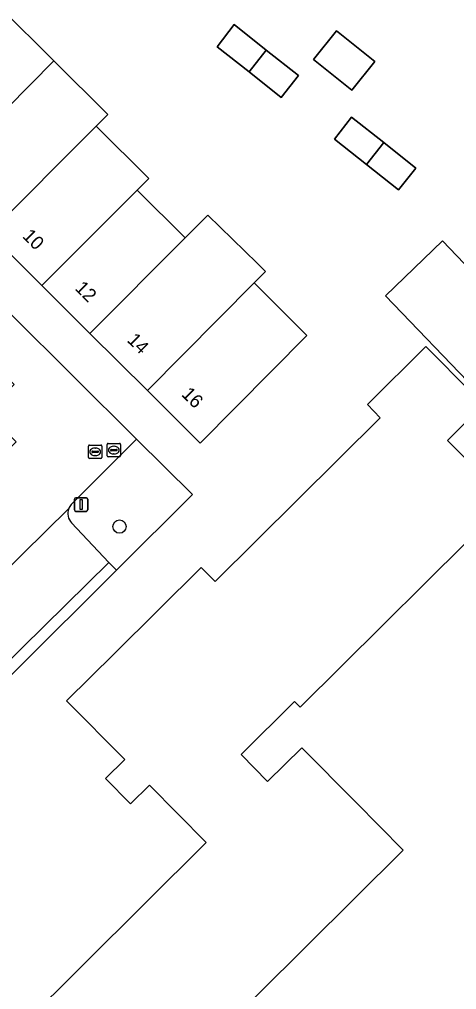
# Model space of a CAD drawing. Extents: x 159217 to 160349, y 381246 to 382172.
# Drawn here: x 160136.7 to 160169.1, y 381809.4 to 381881.2 of the extents above; entities that cross this region are included whole.
import ezdxf

# ---------------------------------------------------------------- set-up
doc = ezdxf.new("R2010")
doc.units = 0
for name, color, linetype in [('IMGEO_Boom', 7, 'Continuous'), ('IMGEO_Erf', 7, 'Continuous'), ('IMGEO_Groenvoorziening', 7, 'Continuous'), ('IMGEO_Lichtmast', 7, 'Continuous'), ('IMGEO_Pand', 7, 'Continuous'), ('IMGEO_Pand_nummerreeks', 7, 'Continuous'), ('IMGEO_Parkeervlak_open', 7, 'Continuous'), ('IMGEO_Rijbaan_lokaal_open', 7, 'Continuous'), ('IMGEO_Rioolput', 7, 'Continuous')]:
    doc.layers.add(name, color=color, linetype=linetype)

msp = doc.modelspace()

# ---------------------------------------------------------------- linework, layer by layer
at = {"layer": 'IMGEO_Boom'}
msp.add_circle((160144.146, 381843.679), 0.489, dxfattribs=at)
at = {"layer": 'IMGEO_Erf'}
for points in [[(160135.289, 381882.107), (160139.285, 381878.145), (160143.281, 381874.182), (160142.426, 381873.326), (160146.318, 381869.443), (160145.46, 381868.584), (160149.006, 381865.046), (160150.699, 381866.743), (160154.339, 381863.189), (160154.967, 381862.561), (160154.123, 381861.711), (160158.032, 381857.827), (160150.125, 381849.867), (160146.217, 381853.749), (160141.958, 381857.981), (160138.4, 381861.516), (160134.5, 381865.391), (160130.54, 381869.325), (160126.548, 381873.292), (160122.556, 381877.258), (160118.566, 381881.222), (160122.789, 381885.483)], [(160113.448, 381881.888), (160122.049, 381873.351), (160145.414, 381850.161), (160149.552, 381846.054), (160143.934, 381840.463), (160128.998, 381825.598), (160127.968, 381824.573), (160119.351, 381815.997), (160108.166, 381805.405)], [(160170.544, 381853.806), (160163.848, 381860.771), (160168.067, 381864.827), (160171.262, 381861.503)], [(160132.354, 381802.21), (160150.581, 381820.291), (160146.369, 381824.537), (160144.966, 381823.146), (160143.105, 381825.021), (160144.532, 381826.436), (160140.234, 381830.77), (160143.784, 381834.292), (160150.198, 381840.654), (160151.235, 381839.608), (160163.467, 381851.742), (160162.511, 381852.705), (160166.847, 381857.005), (160170.276, 381853.549)], [(160171.111, 381852.706), (160168.443, 381850.059), (160172.909, 381845.556), (160157.539, 381830.31), (160157.119, 381830.734), (160153.152, 381826.799), (160155.124, 381824.811), (160157.648, 381827.314), (160161.653, 381823.277), (160165.174, 381819.727), (160140.052, 381794.807)]]:
    msp.add_lwpolyline(points, dxfattribs=at)
for points in [[(160151.385, 381879.202), (160152.631, 381880.839), (160155.019, 381878.952), (160157.407, 381877.065), (160156.132, 381875.451), (160153.744, 381877.338)], [(160158.532, 381878.263), (160160.228, 381880.375), (160163.054, 381878.105), (160161.359, 381875.993)], [(160160.075, 381872.356), (160161.338, 381873.983), (160163.719, 381872.102), (160166.099, 381870.221), (160164.822, 381868.605), (160162.442, 381870.486)]]:
    msp.add_lwpolyline(points, close=True, dxfattribs=at)
at = {"layer": 'IMGEO_Groenvoorziening'}
for points in [[(160145.414, 381850.161), (160140.579, 381845.323)], [(160140.604, 381843.948), (160143.366, 381841.03), (160143.934, 381840.463), (160149.552, 381846.054), (160145.414, 381850.161)]]:
    msp.add_lwpolyline(points, dxfattribs=at)
msp.add_lwpolyline([(160143.934, 381840.463), (160143.366, 381841.03), (160127.317, 381825.26), (160127.968, 381824.573), (160128.998, 381825.598)], close=True, dxfattribs=at)
for centre, radius, start, end in [((160141.315, 381844.649), 0.999, 158.51437, 224.58012), ((160141.338, 381844.633), 1.026, 137.72838, 158.12718)]:
    msp.add_arc(centre, radius, start, end, dxfattribs=at)
at = {"layer": 'IMGEO_Lichtmast'}
for p, q in [((160140.804, 381844.908), (160140.804, 381845.708)), ((160140.804, 381845.708), (160140.804, 381844.908)), ((160140.904, 381845.808), (160141.694, 381845.808)), ((160141.694, 381845.808), (160140.904, 381845.808)), ((160141.794, 381845.708), (160141.794, 381844.908)), ((160141.794, 381844.908), (160141.794, 381845.708)), ((160141.694, 381844.808), (160140.904, 381844.808)), ((160140.904, 381844.808), (160141.694, 381844.808))]:
    msp.add_line(p, q, dxfattribs=at)
msp.add_lwpolyline([(160141.224, 381845.683), (160141.374, 381845.683), (160141.374, 381844.933), (160141.224, 381844.933), (160141.224, 381845.683)], dxfattribs=at)
for centre, start, end in [((160140.904, 381845.708), 90, 180), ((160140.904, 381845.708), 90, 180), ((160141.694, 381845.708), 0, 90), ((160141.694, 381845.708), 360, 90), ((160140.904, 381844.908), 180, 270), ((160140.904, 381844.908), 180, 270), ((160141.694, 381844.908), 270, 0), ((160141.694, 381844.908), 270, 0)]:
    msp.add_arc(centre, 0.1, start, end, dxfattribs=at)
at = {"layer": 'IMGEO_Pand'}
for points in [[(160139.285, 381878.145), (160135.289, 381882.107), (160126.548, 381873.292), (160130.54, 381869.325)], [(160152.631, 381880.839), (160151.385, 381879.202), (160153.744, 381877.338), (160155.019, 381878.952)], [(160158.532, 381878.263), (160161.359, 381875.993), (160163.054, 381878.105), (160160.228, 381880.375)], [(160155.019, 381878.952), (160153.744, 381877.338), (160156.132, 381875.451), (160157.407, 381877.065)], [(160142.426, 381873.326), (160143.281, 381874.182), (160139.285, 381878.145), (160130.54, 381869.325), (160134.5, 381865.391)], [(160161.338, 381873.983), (160160.075, 381872.356), (160162.442, 381870.486), (160163.719, 381872.102)], [(160145.46, 381868.584), (160146.318, 381869.443), (160142.426, 381873.326), (160134.5, 381865.391), (160138.4, 381861.516)], [(160163.719, 381872.102), (160162.442, 381870.486), (160164.822, 381868.605), (160166.099, 381870.221)], [(160149.006, 381865.046), (160145.46, 381868.584), (160138.4, 381861.516), (160141.958, 381857.981)], [(160154.123, 381861.711), (160154.967, 381862.561), (160154.339, 381863.189), (160150.699, 381866.743), (160149.006, 381865.046), (160141.958, 381857.981), (160146.217, 381853.749)], [(160163.848, 381860.771), (160170.544, 381853.806), (160174.763, 381857.862), (160171.262, 381861.503), (160168.067, 381864.827)], [(160158.032, 381857.827), (160154.123, 381861.711), (160146.217, 381853.749), (160150.125, 381849.867)]]:
    msp.add_lwpolyline(points, close=True, dxfattribs=at)
for points in [[(160170.276, 381853.549), (160166.847, 381857.005), (160162.511, 381852.705), (160163.467, 381851.742), (160151.235, 381839.608), (160150.198, 381840.654), (160143.784, 381834.292), (160140.234, 381830.77), (160144.532, 381826.436), (160143.105, 381825.021), (160144.966, 381823.146), (160146.369, 381824.537), (160150.581, 381820.291), (160132.354, 381802.21)], [(160140.052, 381794.807), (160165.174, 381819.727), (160161.653, 381823.277), (160157.648, 381827.314), (160155.124, 381824.811), (160153.152, 381826.799), (160157.119, 381830.734), (160157.539, 381830.31), (160172.909, 381845.556), (160168.443, 381850.059), (160171.111, 381852.706)]]:
    msp.add_lwpolyline(points, dxfattribs=at)
at = {"layer": 'IMGEO_Parkeervlak_open'}
for points in [[(160140.386, 381845.015), (160124.93, 381829.819), (160123.177, 381828.096)], [(160124.452, 381828.075), (160127.008, 381825.563), (160127.317, 381825.26), (160143.366, 381841.03), (160140.604, 381843.948)]]:
    msp.add_lwpolyline(points, dxfattribs=at)
msp.add_arc((160141.315, 381844.649), 0.999, 158.51437, 224.58012, dxfattribs=at)
at = {"layer": 'IMGEO_Rijbaan_lokaal_open'}
for points in [[(160122.049, 381873.351), (160119.917, 381871.221), (160119.501, 381870.804), (160118.769, 381870.052), (160117.637, 381868.956), (160121.731, 381864.845), (160123.668, 381866.777), (160129.196, 381861.275), (160130.087, 381860.444), (160136.344, 381854.192), (160134.193, 381852.151), (160136.491, 381849.949), (160120.656, 381834.07), (160124.93, 381829.819), (160140.386, 381845.015)], [(160140.579, 381845.323), (160145.414, 381850.161), (160122.049, 381873.351)]]:
    msp.add_lwpolyline(points, dxfattribs=at)
msp.add_arc((160141.338, 381844.633), 1.026, 137.72838, 158.12718, dxfattribs=at)
at = {"layer": 'IMGEO_Rioolput'}
for p, q in [((160141.922, 381849.717), (160142.774, 381849.717)), ((160143.229, 381848.915), (160143.229, 381849.767)), ((160143.304, 381849.841), (160144.156, 381849.841)), ((160144.23, 381849.767), (160144.23, 381848.915)), ((160141.847, 381848.791), (160141.847, 381849.643)), ((160142.106, 381849.211), (160142.106, 381849.223)), ((160142.544, 381849.174), (160142.146, 381849.174)), ((160142.149, 381849.26), (160142.547, 381849.26)), ((160142.335, 381849.497), (160142.36, 381849.497)), ((160142.59, 381849.223), (160142.59, 381849.211)), ((160142.848, 381849.643), (160142.848, 381848.791)), ((160143.488, 381849.335), (160143.488, 381849.347)), ((160143.926, 381849.298), (160143.528, 381849.298)), ((160143.531, 381849.384), (160143.929, 381849.384)), ((160143.74, 381849.061), (160143.715, 381849.061)), ((160143.717, 381849.621), (160143.742, 381849.621)), ((160143.972, 381849.347), (160143.972, 381849.335)), ((160142.774, 381848.717), (160141.922, 381848.717)), ((160142.358, 381848.937), (160142.333, 381848.937)), ((160144.156, 381848.841), (160143.304, 381848.841))]:
    msp.add_line(p, q, dxfattribs=at)
for points in [[(160141.922, 381849.717), (160142.774, 381849.717)], [(160143.229, 381848.915), (160143.229, 381849.767)], [(160143.304, 381849.841), (160144.156, 381849.841)], [(160144.23, 381849.767), (160144.23, 381848.915)], [(160141.847, 381848.791), (160141.847, 381849.643)], [(160142.848, 381849.643), (160142.848, 381848.791)], [(160142.774, 381848.717), (160141.922, 381848.717)], [(160144.156, 381848.841), (160143.304, 381848.841)]]:
    msp.add_lwpolyline(points, dxfattribs=at)
for centre, radius, start, end in [((160141.924, 381849.641), 0.0765, 91.55205, 178.44795), ((160141.924, 381849.641), 0.0765, 91.55205, 178.44795), ((160142.772, 381849.641), 0.0765, 1.55205, 88.44795), ((160142.772, 381849.641), 0.0765, 1.55205, 88.44795), ((160143.306, 381849.765), 0.0765, 91.55205, 178.44795), ((160143.306, 381849.765), 0.0765, 91.55205, 178.44795), ((160144.154, 381849.765), 0.0765, 1.55205, 88.44795), ((160144.154, 381849.765), 0.0765, 1.55205, 88.44795), ((160142.146, 381849.22), 0.0403, 85.87752, 175.75265), ((160142.143, 381849.21), 0.0366, 178.93798, 274.71019), ((160142.547, 381849.217), 0.043, 264.86636, 352.45326), ((160142.551, 381849.222), 0.0386, 1.73085, 96.63898), ((160143.528, 381849.344), 0.0403, 85.87752, 175.75265), ((160143.525, 381849.334), 0.0366, 178.93798, 274.71019), ((160143.929, 381849.341), 0.043, 264.86636, 352.45326), ((160143.933, 381849.346), 0.0386, 1.73085, 96.63898), ((160141.924, 381848.793), 0.0765, 181.55205, 268.44795), ((160141.924, 381848.793), 0.0765, 181.55205, 268.44795), ((160142.772, 381848.793), 0.0765, 271.55205, 358.44795), ((160142.772, 381848.793), 0.0765, 271.55205, 358.44795), ((160143.306, 381848.917), 0.0765, 181.55205, 268.44795), ((160143.306, 381848.917), 0.0765, 181.55205, 268.44795), ((160144.154, 381848.917), 0.0765, 271.55205, 358.44795), ((160144.154, 381848.917), 0.0765, 271.55205, 358.44795)]:
    msp.add_arc(centre, radius, start, end, dxfattribs=at)
for centre, major_axis, ratio, start_param, end_param in [((160142.334, 381849.217), (-0.387, 0.002), 0.722429, 4.712389, 7.853982), ((160142.359, 381849.217), (-0.39, 0.002), 0.717154, 1.570796, 4.712389), ((160143.716, 381849.341), (-0.387, 0.002), 0.722429, 4.712389, 7.853982), ((160143.741, 381849.341), (-0.39, 0.002), 0.717154, 1.570796, 4.712389)]:
    msp.add_ellipse(centre, major_axis=major_axis, ratio=ratio, start_param=start_param, end_param=end_param, dxfattribs=at)

# ---------------------------------------------------------------- texts
at = {"layer": 'IMGEO_Pand_nummerreeks'}
for s, p in [('10', (160136.9, 381865.121)), ('12', (160140.788, 381861.258)), ('14', (160144.656, 381857.415)), ('16', (160148.687, 381853.41))]:
    msp.add_text(s, height=1, rotation=315.18324, dxfattribs=at).set_placement(p)

doc.saveas('drawing.dxf')
